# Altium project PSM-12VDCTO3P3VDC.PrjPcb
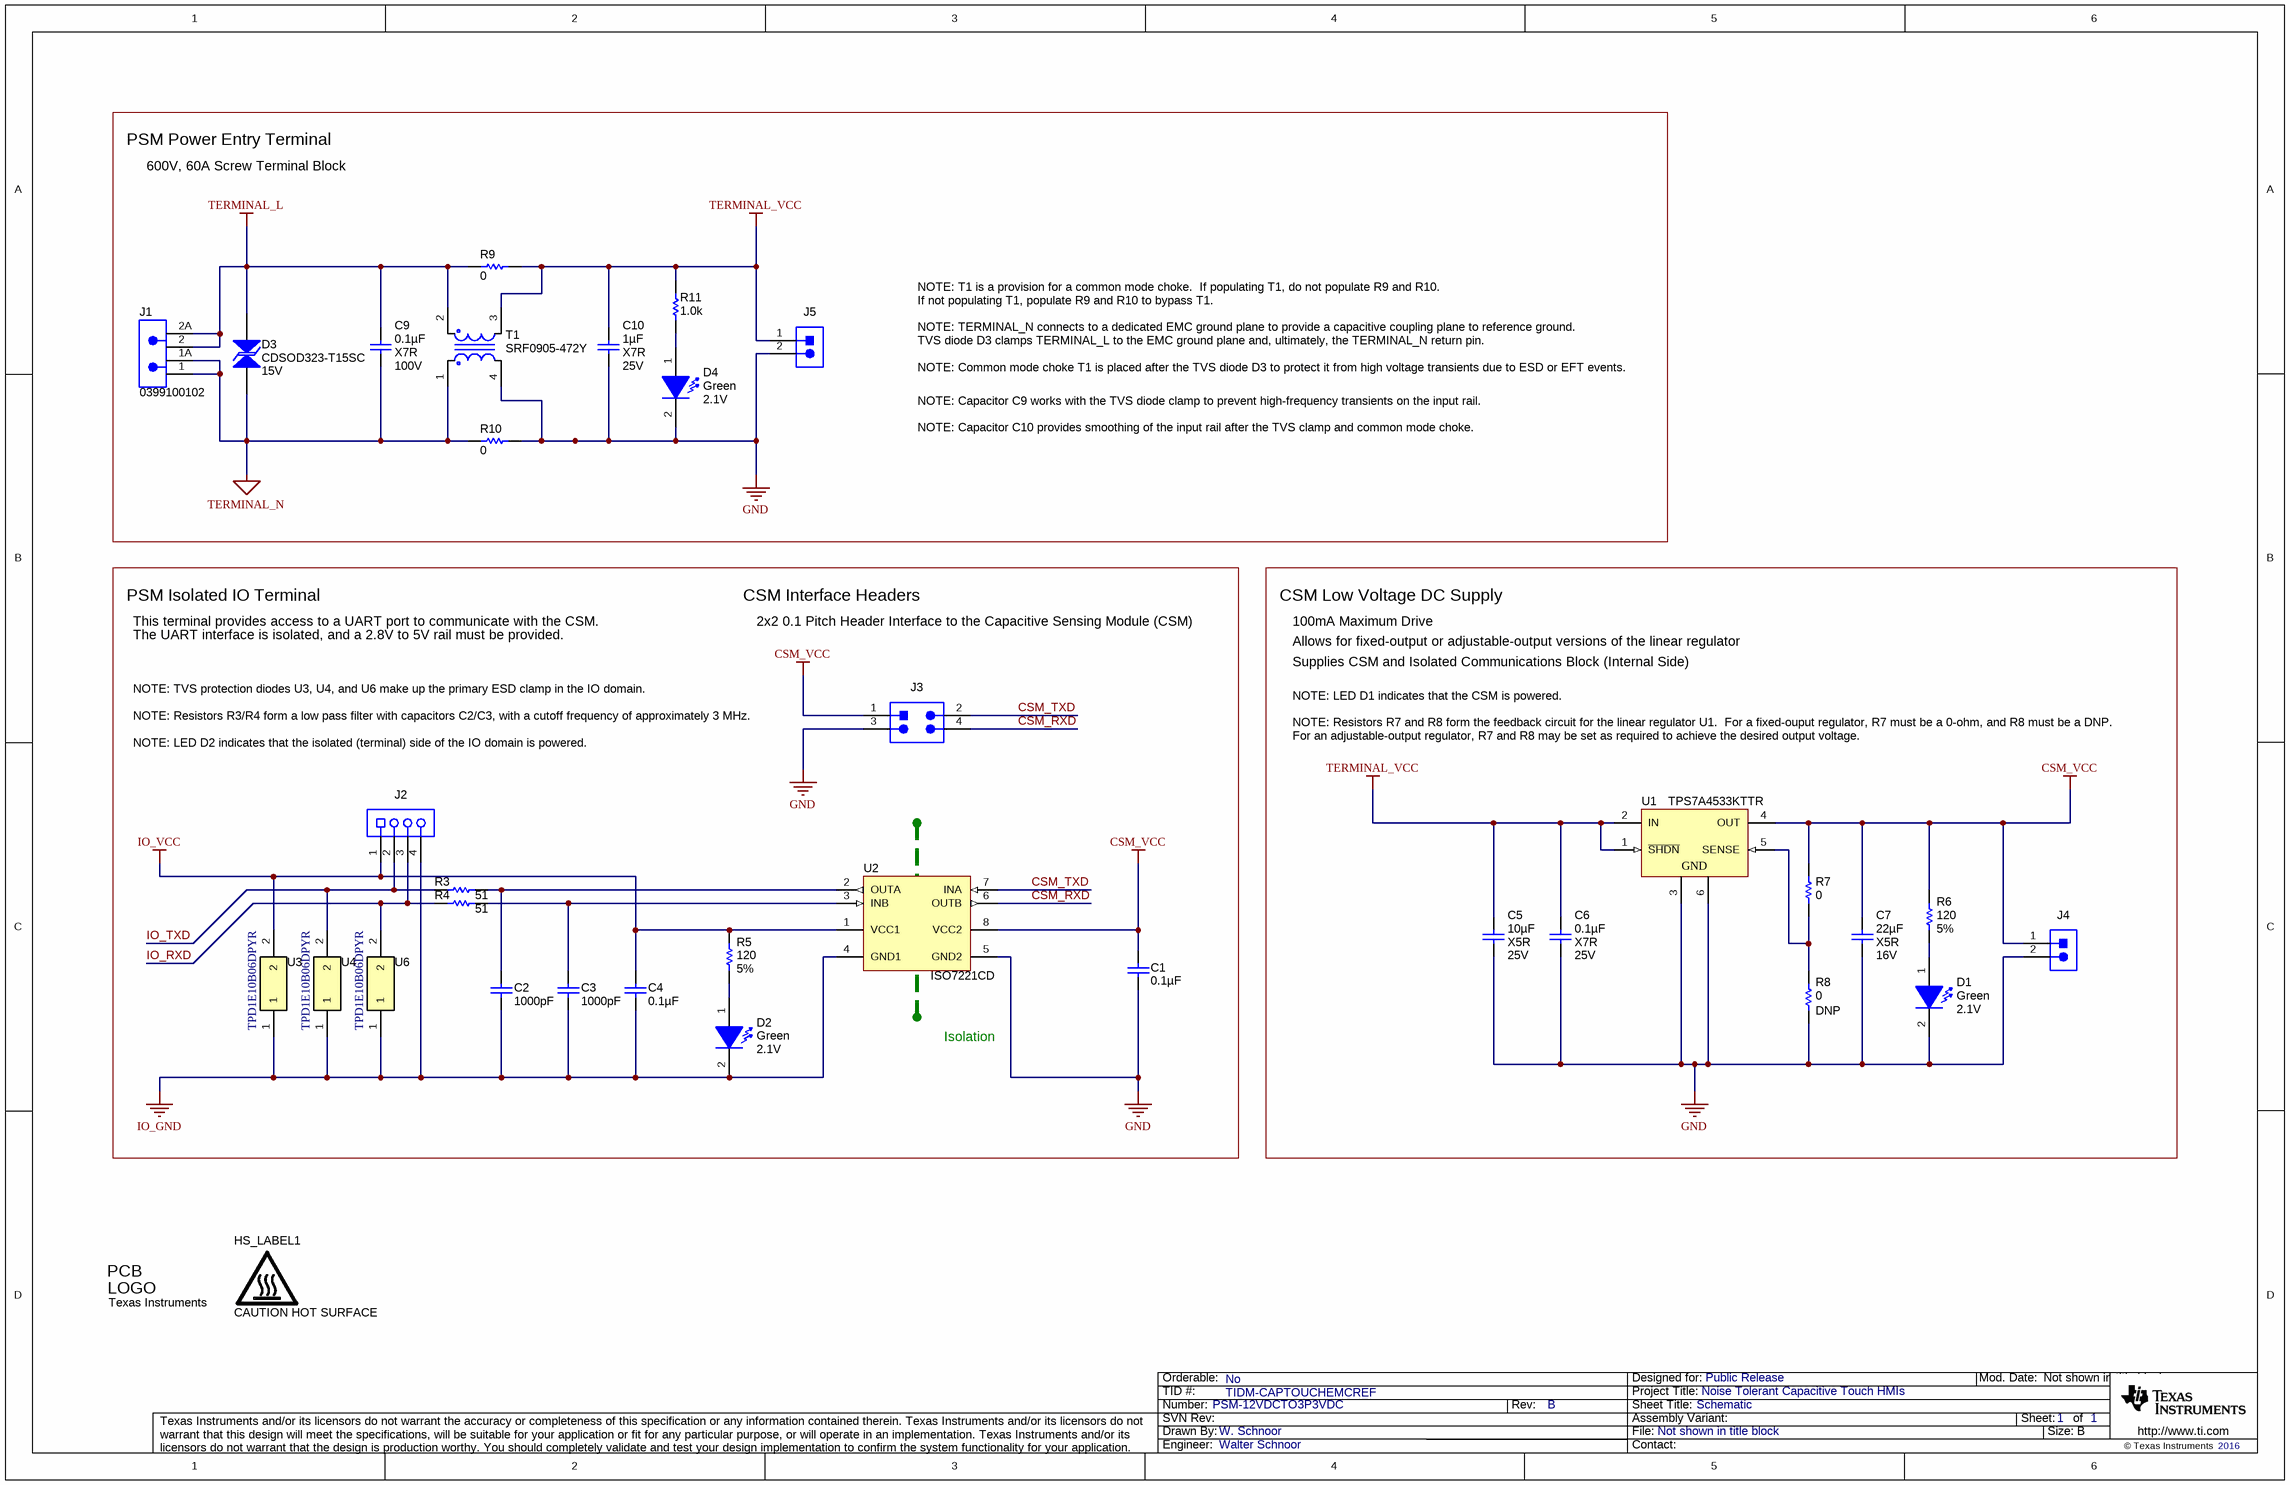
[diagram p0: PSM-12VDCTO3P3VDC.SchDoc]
TID: TIDM-CAPTOUCHEMCREF; SCH_Rev: B; PRJ_Title: Noise Tolerant Capacitive Touch HMIs; PRJ_Number: PSM-12VDCTO3P3VDC; PRJ_Engineer: Walter Schnoor; PRJ_Customer: Public Release; PCB_Rev: B; PCB_Layout: Walter Schnoor; EVM_Orderable: No; CopyrightYear: 2016
1 sheet, 35 parts. Net scope: global (net labels, ports and power ports of the same name join across sheets).
Board file: PSM-12VDCTO3P3VDC.PcbDoc

## Sheet PSM-12VDCTO3P3VDC.SchDoc: Schematic
size 431 x 279 mm; Date: Not shown in title block; ApprovedBy: Not shown in title block; CheckedBy: Not shown in title block; Author: Not shown in title block; CompanyName: Not shown in title block; DrawnBy: W. Schnoor; Engineer: Not shown in title block; Organization: Not shown in title block; Address1: Not shown in title block; Address2: Not shown in title block; Address3: Not shown in title block; Address4: Not shown in title block; DocumentNumber: 1; Revision: Use project parameter SCH_Rev; SheetNumber: 1; SheetTotal: 1; PageSetup: Record=PageOptions¦CenterHorizontal=True¦CenterVertical=True¦PrintScale=0.62¦XCorrection=1.00¦YCorrection=1.00¦PrintKind=0¦BorderSize=5000000¦LeftOffset=0¦BottomOffset=0¦Orientation=2¦PaperLength=1000¦PaperWidth=1000¦Scale=100¦PaperSource=15¦PrintQuality=600¦MediaType=1¦DitherType=10¦PrintScaleMode=1¦PaperKind=Letter¦PaperIndex=1

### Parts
C1  ValueDisplayed: 0.1µF  [0603]  (hidden comment: GRM188R71C104KA01D)
C2  ValueDisplayed: 1000pF  [0603]  (hidden comment: 06031C102JAT2A)
C3  ValueDisplayed: 1000pF  [0603]  (hidden comment: 06031C102JAT2A)
C4  ValueDisplayed: 0.1µF  [0603]  (hidden comment: GRM188R71C104KA01D)
C5  ValueDisplayed: 10µF  Value2: 25V  TempCo: X5R  [0805_HV]  (hidden comment: C2012X5R1E106K125AB)
C6  ValueDisplayed: 0.1µF  Value2: 25V  TempCo: X7R  [0805_HV]  (hidden comment: 08053C104KAT2A)
C7  ValueDisplayed: 22µF  Value2: 16V  TempCo: X5R  [0805_HV]  (hidden comment: C2012X5R1C226K125AC)
C9  ValueDisplayed: 0.1µF  Value2: 100V  TempCo: X7R  [1206]  (hidden comment: 12061C104KAT2A)
C10  ValueDisplayed: 1µF  Value2: 25V  TempCo: X7R  [1206]  (hidden comment: 12063C105KAT2A)
D1  value Green  Value2: 2.1V  [HLMP-351_GREEN]  (hidden comment: HLMP-3519)
D2  value Green  Value2: 2.1V  [HLMP-351_GREEN]  (hidden comment: HLMP-3519)
D3  CDSOD323-T15SC  value 15V  [SOD-323-Bi]
D4  value Green  Value2: 2.1V  [HLMP-351_GREEN]  (hidden comment: HLMP-3519)
HS_LABEL1  CAUTION HOT SURFACE  [IEC_HotSurface_Small]  (no BOM)
J1  0399100102  [CONN_399100102]
J2  39544-3004  [MOLEX_39544-3004]  (value not drawn)
J3  PEC02DAAN  [Sullins_PEC02DAAN]  (value not drawn)
J4  HTSW-102-07-G-S  [Samtec_HTSW-102-07-G-S]  (value not drawn)
J5  HTSW-102-07-G-S  [Samtec_HTSW-102-07-G-S]  (value not drawn)
LOGO2  Texas Instruments  [TI_Horizontal_Overlay_Medium]  (no BOM)
R3  ValueDisplayed: 51  [0603]  (hidden comment: CRCW060351R0JNEA)
R4  ValueDisplayed: 51  [0603]  (hidden comment: CRCW060351R0JNEA)
R5  ValueDisplayed: 120  Value1: 5%  [0603]  (hidden comment: CRCW0603120RJNEA)
R6  ValueDisplayed: 120  Value1: 5%  [0603]  (hidden comment: CRCW0603120RJNEA)
R7  value 0  [0805_HV]  (hidden comment: CRCW08050000Z0EA)
R8  value 0  [0805_HV]  (hidden comment: CRCW08050000Z0EA)
R9  ValueDisplayed: 0  [1206]  (hidden comment: CRCW12060000Z0EA)
R10  ValueDisplayed: 0  [1206]  (hidden comment: CRCW12060000Z0EA)
R11  ValueDisplayed: 1.0k  [1206]  (hidden comment: CRCW12061K00JNEA)
T1  SRF0905-472Y  [SRF0905]
U1  TPS7A4533KTTR  [KTT0005A_N]
U2  ISO7221CD  [D0008A_N]
U3  TPD1E10B06DPYR  [DPY0002A]
U4  TPD1E10B06DPYR  [DPY0002A]
U6  TPD1E10B06DPYR  [DPY0002A]

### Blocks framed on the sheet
PSM Power Entry Terminal: C9 C10 D3 D4 J1 J5 R9-R11 T1
CSM Low Voltage DC Supply: C5-C7 D1 J4 R6-R8 U1

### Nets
CSM_VCC: C1.1 C7.1 J3.1 J4.1 R6.2 R7.2 U1.4(OUT) U2.8(VCC2)
GND: C1.2 C5.2 C6.2 C7.2 C10.2 D1.2(K) D4.2(K) J3.3 J4.2 J5.2 R8.1 R10.2 T1.4 U1.3(GND) U1.6(GND) U2.5(GND2)
IO_GND: C2.2 C3.2 C4.2 D2.2(K) J2.4 U2.4(GND1) U3.1 U4.1 U6.1
IO_VCC: C4.1 J2.1 R5.2 U2.1(VCC1) U3.2
TERMINAL_L: C9.1 D3.2 J1.2 J1.2A R9.1 T1.2
TERMINAL_N: C9.2 D3.1 J1.1 J1.1A R10.1 T1.1
TERMINAL_VCC: C5.1 C6.1 C10.1 J5.1 R9.2 R11.2 T1.3 U1.1(~{SHDN}) U1.2(IN)
CSM_RXD: J3.4 U2.6(OUTB)
CSM_TXD: J3.2 U2.7(INA)
IO_RXD: J2.3 R4.1 U6.2
IO_TXD: J2.2 R3.1 U4.2
NetC2_1: C2.1 R3.2 U2.2(OUTA)
NetC3_1: C3.1 R4.2 U2.3(INB)
NetD1_1: D1.1(A) R6.1
NetD2_1: D2.1(A) R5.1
NetD4_1: D4.1(A) R11.1
NetR7_1: R7.1 R8.2 U1.5(SENSE)

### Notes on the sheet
- 600V, 60A Screw Terminal Block
- NOTE: T1 is a provision for a common mode choke.  If populating T1, do not populate R9 and R10.
- If not populating T1, populate R9 and R10 to bypass T1.
- NOTE: TERMINAL_N connects to a dedicated EMC ground plane to provide a capacitive coupling plane to reference ground.
- TVS diode D3 clamps TERMINAL_L to the EMC ground plane and, ultimately, the TERMINAL_N return pin.
- NOTE: Common mode choke T1 is placed after the TVS diode D3 to protect it from high voltage transients due to ESD or EFT events.
- NOTE: Capacitor C10 provides smoothing of the input rail after the TVS clamp and common mode choke.
- NOTE: Capacitor C9 works with the TVS diode clamp to prevent high-frequency transients on the input rail.
- PSM Isolated IO Terminal
- This terminal provides access to a UART port to communicate with the CSM.
- The UART interface is isolated, and a 2.8V to 5V rail must be provided.
- CSM Interface Headers
- 2x2 0.1 Pitch Header Interface to the Capacitive Sensing Module (CSM)
- 100mA Maximum Drive
- NOTE: TVS protection diodes U3, U4, and U6 make up the primary ESD clamp in the IO domain.
- Allows for fixed-output or adjustable-output versions of the linear regulator
- Supplies CSM and Isolated Communications Block (Internal Side)
- NOTE: LED D1 indicates that the CSM is powered.
- NOTE: Resistors R3/R4 form a low pass filter with capacitors C2/C3, with a cutoff frequency of approximately 3 MHz.
- NOTE: LED D2 indicates that the isolated (terminal) side of the IO domain is powered.
- NOTE: Resistors R7 and R8 form the feedback circuit for the linear regulator U1.  For a fixed-ouput regulator, R7 must be a 0-ohm, and R8 must be a DNP.
- For an adjustable-output regulator, R7 and R8 may be set as required to achieve the desired output voltage.
- Isolation
- (near R8) DNP

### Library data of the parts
C1 C4 = GRM188R71C104KA01D: CAP, CERM, 0.1 µF, 16 V, +/- 10%, X7R, 0603; Manufacturer: MuRata; Polarized: N; CompType: Capacitor; Value: 0.1uF; U/M: EA; Cap_F: 0.0000001; Tolerance_%: 10; Value1: Unknown; VDC_V: 16; Value2: 16V; TaMin_C: -55; TaMax_C: 125
C2 C3 = 06031C102JAT2A: CAP, CERM, 1000 pF, 100 V, +/- 5%, X7R, 0603; Manufacturer: AVX; Polarized: N; CompType: Capacitor; Value: 1000pF; U/M: EA; Cap_F: 0.000000001; Tolerance_%: 5; ESR_ohm: 0.276; Value1: 0.276 ohm; VDC_V: 100; Value2: 100V; TaMin_C: -55; TaMax_C: 125
C5 = C2012X5R1E106K125AB: CAP, CERM, 10 µF, 25 V, +/- 10%, X5R, 0805; Manufacturer: TDK; Polarized: N; CompType: Capacitor; Value: 10uF; U/M: EA; Cap_F: 0.00001; Tolerance_%: 10; Value1: Unknown; VDC_V: 25; TaMin_C: -55; TaMax_C: 85; Cap_Case: 0805
C6 = 08053C104KAT2A: CAP, CERM, 0.1 µF, 25 V, +/- 10%, X7R, 0805; Manufacturer: AVX; Polarized: N; CompType: Capacitor; Value: 0.1uF; U/M: EA; Cap_F: 0.0000001; Tolerance_%: 10; ESR_ohm: 0.28; Value1: 0.28 ohm; VDC_V: 25; TaMin_C: -55; TaMax_C: 125; Cap_Case: 0805
C7 = C2012X5R1C226K125AC: CAP, CERM, 22 µF, 16 V, +/- 10%, X5R, 0805; Manufacturer: TDK; Polarized: N; CompType: Capacitor; Value: 22uF; U/M: EA; Cap_F: 0.000022; Tolerance_%: 10; Value1: Unknown; VDC_V: 16; TaMin_C: -55; TaMax_C: 85; Cap_Case: 0805
C9 = 12061C104KAT2A: CAP, CERM, 0.1 µF, 100 V, +/- 10%, X7R, 1206; Manufacturer: AVX; Polarized: N; CompType: Capacitor; Value: 0.1uF; U/M: EA; Cap_F: 0.0000001; Tolerance_%: 10; ESR_ohm: 0.037; Value1: 0.037 ohm; VDC_V: 100; TaMin_C: -55; TaMax_C: 125
C10 = 12063C105KAT2A: CAP, CERM, 1 µF, 25 V, +/- 10%, X7R, 1206; Manufacturer: AVX; Polarized: N; CompType: Capacitor; Value: 1uF; U/M: EA; Cap_F: 0.000001; Tolerance_%: 10; ESR_ohm: 0.013; Value1: 0.013 ohm; VDC_V: 25; TaMin_C: -55; TaMax_C: 125
D1 D2 D4 = HLMP-3519: LED, Green, TH; Manufacturer: Avago; Vf_V: 2.1; Io_A: 0.01; Tjmax_C: 110; Value1: W; U/M: EA
D3 = CDSOD323-T15SC: Diode, TVS, Bi, 15 V, 400 W, SOD323, 2-Leads, Body 1.9x1.45mm, No Polarity Mark; Manufacturer: Bourns; U/M: EA; Power_W: 400; Vr_V: 15; Value1: 400W
HS_LABEL1 = IEC_HotSurface: IEC 61010-1 Hot Surface Warning; SymbolCreator: a0412235
J1 = 0399100102: Terminal Block, 60A, 10.16mm Pitch, 2-Pos, TH; Manufacturer: Molex; SymbolCreator: a0799628; CompType: Connector; U/M: EA
J2 = 39544-3004: Terminal Block, 4x1, 5.08mm, TH; Manufacturer: Molex; SymbolCreator: a0411947; U/M: EA
J3 = PEC02DAAN: Header, 100mil, 2x2, Tin, TH; Manufacturer: Sullins Connector Solutions; SymbolCreator: a0412235; U/M: EA
J4 J5 = HTSW-102-07-G-S: Header, 100mil, 2x1, Gold, TH; Manufacturer: Samtec; SymbolCreator: a0412235; U/M: EA
LOGO2 = TI_Logo: Texas Instrument Corporate Signature; SymbolCreator: a0412235
R3 R4 = CRCW060351R0JNEA: RES, 51, 5%, 0.1 W, 0603; Manufacturer: Vishay-Dale; CompType: Resistor; Value: 51; Value_Code: 51R0; Tolerance_%: 5; Power_W: 0.1; Value2: 0.1W; VDC_V: 75; TempCo: 200 ppm/C; EIA_Code: E24; U/M: EA
R5 R6 = CRCW0603120RJNEA: RES, 120, 5%, 0.1 W, 0603; Manufacturer: Vishay-Dale; CompType: Resistor; Value: 120; Value_Code: 120R; Tolerance_%: 5; Power_W: 0.1; Value2: 0.1W; VDC_V: 75; TempCo: 200 ppm/C; EIA_Code: E24; U/M: EA
R7 R8 = CRCW08050000Z0EA: RES, 0 ohm, 5%, 0.125W, 0805; Manufacturer: Vishay-Dale; CompType: Resistor; Value_Code: 0000; Tolerance_%: 5; Power_W: 0.125; VDC_V: 150; TempCo: 200 ppm/C; EIA_Code: E24; U/M: EA
R9 R10 = CRCW12060000Z0EA: RES, 0, 5%, 0.25 W, 1206; Manufacturer: Vishay-Dale; CompType: Resistor; Value: 0; Value_Code: 0000; Tolerance_%: 5; Power_W: 0.25; Value2: 0.25W; VDC_V: 200; TempCo: 200 ppm/C; EIA_Code: E24; U/M: EA
R11 = CRCW12061K00JNEA: RES, 1.0 k, 5%, 0.25 W, 1206; Manufacturer: Vishay-Dale; CompType: Resistor; Value: 1.0k; Res_ohm: 1000; Value_Code: 1k00; Tolerance_%: 5; Power_W: 0.25; Value2: 0.25W; VDC_V: 200; TempCo: 200 ppm/C; EIA_Code: E24; U/M: EA
T1 = SRF0905-472Y: Line Filter; Manufacturer: Bourns; Alternate Manufacturer: None; CompType: Transformer; DCR_Ohm: 0.9; VDC_V: 50; Value: 4700 uH; LeakageL: 0.36; Imax_A: 0.4; Ind_H: 4.7E-3; U/M: EA
U1 = TPS7A4533KTTR: Single Output Fast Transient Response LDO, 1.5 A, Fixed 3.3 V Output, 2.1 to 20 V Input, 5-pin DDPAK (KTT), -40 to 125 degC, Green (RoHS & no Sb/Br); Manufacturer: Texas Instruments; Alternate Manufacturer: None; Alternate PartNumber: Equivalent; Accuracy(%): 1; Fixed Output Options(V): 3.3; Iout(Max)(A): 1.5; SubFamily: Single Channel LDO; Vdo(Typ)(mV): 300; Vin(Max)(V): 20; Vin(Min)(V): 2.1
U2 = ISO7221CD: 25 Mbps Dual Channels, 1 / 1, Digital Isolator, 3.3 V / 5 V, -40 to +125 degC, 8-pin SOIC (D), Green (RoHS & no Sb/Br); Manufacturer: Texas Instruments; Alternate Manufacturer: None; Alternate PartNumber: Equivalent; Datarate(Mbps): 25; Input Noise Filter: Yes; Insulation Rating(VRMS): 2500; Prop Delay(Max)(ns): 42; Rating: Catalog; Supply Voltage(s)(V): 3.3, 5; TTL/CMOS Input Threshold: TTL
U3 U4 U6 = TPD1E10B06DPYR: ESD in 0402 Package with 10 pF Capacitance and 6 V Breakdown, 1 Channel, -40 to +125 degC, 2-pin X2SON (DPY), Green (RoHS & no Sb/Br); Manufacturer: Texas Instruments; Alternate PartNumber: Equivalent; Breakdown Voltage(Min)(V): 6; Eco-Plan: TBD; IEC 61000-4-2 Air-Gap(+/- kV): 30; IO Capacitance(Typ)(pF): 10; SubFamily: ESD Solution

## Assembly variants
Without CMC: not fitted T1
With CMC: not fitted R9 R10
